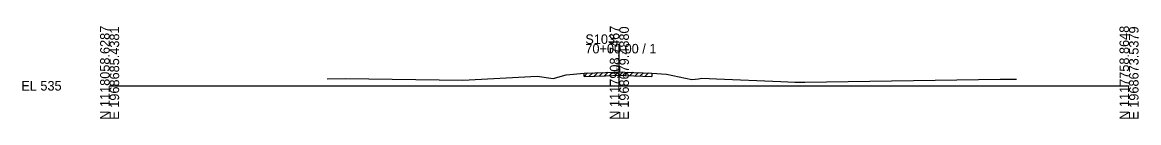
# Model space of a CAD drawing. Extents: x 974 to 1303, y 990 to 14518.
# Drawn here: x 974.3 to 1302.8, y 11490.3 to 11517.5 of the extents above; entities that cross this region are included whole.
import ezdxf

# ---------------------------------------------------------------- set-up
doc = ezdxf.new("R2010")
doc.units = 0
for name, color, linetype in [('Level 10', 7, 'Continuous'), ('Level 60', 7, 'Continuous'), ('Level 61', 7, 'Continuous'), ('Level 63', 7, 'Continuous')]:
    doc.layers.add(name, color=color, linetype=linetype)

msp = doc.modelspace()

# ---------------------------------------------------------------- linework, layer by layer
at = {"layer": 'Level 60'}
for p, q in [((1064.03, 11502.09), (1069.35, 11502.16)), ((1069.35, 11502.16), (1103.98, 11501.68)), ((1103.98, 11501.68), (1125.86, 11502.84)), ((1125.86, 11502.84), (1130.51, 11502.13)), ((1130.51, 11502.13), (1134.34, 11503.21)), ((1134.34, 11503.21), (1139.63, 11503.74)), ((1139.63, 11503.74), (1145.97, 11503.96)), ((1145.97, 11503.96), (1150.14, 11504.11)), ((1150.14, 11504.11), (1151.66, 11504.06)), ((1151.66, 11504.06), (1159.61, 11503.77)), ((1159.61, 11503.77), (1163.87, 11503.39)), ((1163.87, 11503.39), (1171.36, 11501.89)), ((1171.36, 11501.89), (1173.33, 11502.1)), ((1173.33, 11502.1), (1174.26, 11502.2)), ((1174.26, 11502.2), (1178.59, 11502.02)), ((1178.59, 11502.02), (1197.49, 11501.22)), ((1204.56, 11501.08), (1262.11, 11501.95)), ((1262.11, 11501.95), (1266.9, 11501.91)), ((1197.49, 11501.22), (1201.62, 11501.04)), ((1201.62, 11501.04), (1204.56, 11501.08))]:
    msp.add_line(p, q, dxfattribs=at)
at = {"layer": 'Level 61'}
for p, q in [((1139.63, 11502.74), (1140.67, 11503.78)), ((1139.63, 11502.74), (1139.63, 11503.74)), ((1139.63, 11502.74), (1145.97, 11502.96)), ((1139.63, 11502.74), (1139.63, 11502.74)), ((1141.13, 11502.79), (1142.17, 11503.83)), ((1142.63, 11502.85), (1143.67, 11503.88)), ((1144.13, 11502.9), (1145.17, 11503.94)), ((1145.63, 11502.95), (1146.67, 11503.99)), ((1145.97, 11502.96), (1150.14, 11503.11)), ((1147.13, 11503.01), (1148.17, 11504.04)), ((1148.63, 11503.06), (1149.67, 11504.1)), ((1150.13, 11503.11), (1151.1, 11504.08)), ((1150.14, 11503.11), (1151.66, 11503.06)), ((1151.63, 11503.06), (1152.6, 11504.03)), ((1151.66, 11503.06), (1159.61, 11502.77)), ((1153.13, 11503.01), (1154.1, 11503.97)), ((1154.63, 11502.95), (1155.6, 11503.92)), ((1156.13, 11502.9), (1157.1, 11503.86)), ((1157.63, 11502.84), (1158.6, 11503.81)), ((1159.61, 11503.77), (1159.61, 11502.77))]:
    msp.add_line(p, q, dxfattribs=at)
at = {"layer": 'Level 63'}
for p, q in [((1150, 11500), (1150, 11512.34)), ((1000, 11500), (1150, 11500)), ((1150, 11500), (1300, 11500))]:
    msp.add_line(p, q, dxfattribs=at)

# ---------------------------------------------------------------- texts
at = {"layer": 'Level 10'}
msp.add_text('539.11', height=0.9, rotation=90, dxfattribs=at).set_placement((1149.95, 11504.61))
at = {"layer": 'Level 63'}
for s, p in [('N 1118058.6287', (1000, 11490)), ('E 1968685.4381', (1002.8, 11490)), ('N 1117908.7467', (1150, 11490)), ('E 1968679.4880', (1152.8, 11490)), ('N 1117758.8648', (1300, 11490)), ('E 1968673.5379', (1302.8, 11490))]:
    msp.add_text(s, height=2.8, rotation=90, dxfattribs=at).set_placement(p)
for s, p in [('S103', (1140, 11512.34)), ('70+00.00 / 1', (1140, 11509.54)), ('EL 535', (974, 11498.6))]:
    msp.add_text(s, height=2.8, dxfattribs=at).set_placement(p)

doc.saveas('drawing.dxf')
